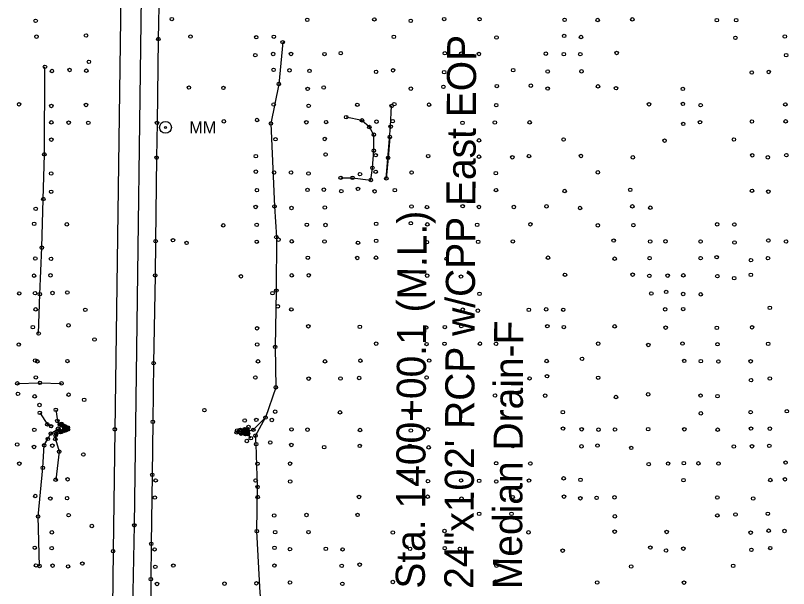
# Model space of a CAD drawing. Extents: x 20503438 to 20508873, y 7964251 to 7984667.
# Drawn here: x 20506686.4 to 20507132.2, y 7972709.2 to 7973039.7 of the extents above; entities that cross this region are included whole.
import ezdxf

# ---------------------------------------------------------------- set-up
doc = ezdxf.new("R2010")
doc.units = 0
for name, color, linetype in [('SurBreakLine', 7, 'Continuous'), ('SurConcreteSlab', 7, 'Continuous'), ('SurDikeDam', 7, 'Continuous'), ('SurDrainageArrowDown', 7, 'Continuous'), ('SurDrainageArrowUp', 7, 'Continuous'), ('SurEdgeRoadPaved', 7, 'Continuous'), ('SurPointsNonDTM', 7, 'Continuous'), ('SurRipRap', 7, 'Continuous'), ('SurRoadPoints', 7, 'Continuous'), ('SurSurveyPoints', 7, 'Continuous'), ('SurTxtDrainage', 7, 'Continuous')]:
    doc.layers.add(name, color=color, linetype=linetype)

msp = doc.modelspace()

# ---------------------------------------------------------------- linework, layer by layer
at = {"layer": 'SurBreakLine'}
for points in [[(20506748.06, 7973121.35), (20506742.68, 7972730.78), (20506738.51, 7972374.69), (20506737.86, 7972337.8), (20506736.71, 7972242.37), (20506735.23, 7972125.23), (20506734.95, 7972091.62), (20506733.69, 7971999.07), (20506733.06, 7971941.23), (20506731.39, 7971811.28), (20506730.1, 7971695.4), (20506729.05, 7971627.9), (20506728.3, 7971561.44), (20506726.5, 7971429.38), (20506726.18, 7971406.05), (20506723.05, 7971149.78), (20506722.41, 7971105.59), (20506719.46, 7970853.94), (20506718.67, 7970817.35), (20506718.46, 7970790.57), (20506717.85, 7970756.37), (20506717.5, 7970726.21), (20506716.72, 7970686.1), (20506716.2, 7970609.97)], [(20506902.29, 7972969.57), (20506901.26, 7972957.53), (20506900.23, 7972945.71), (20506902.74, 7972975.56), (20506903.3, 7972987.46)], [(20506709.69, 7972812.25), (20506710.56, 7972805.83), (20506711.93, 7972803.74), (20506712.96, 7972804.17), (20506716.58, 7972802.08), (20506716.65, 7972800.88), (20506715.37, 7972800.39), (20506713.02, 7972799.51), (20506712.61, 7972799.35), (20506710.67, 7972799.21), (20506709.77, 7972798.39), (20506709.53, 7972797.45), (20506709.4, 7972795.41), (20506711.58, 7972788.13), (20506709.59, 7972771.97)], [(20506822.14, 7972795.93), (20506820.5, 7972798.32), (20506816.48, 7972798.48), (20506813.96, 7972799.22), (20506814.25, 7972800.33), (20506815.9, 7972800.7), (20506818.75, 7972800.97), (20506820.14, 7972800.73), (20506820.73, 7972802.35)], [(20506820.04, 7972800.39), (20506818.39, 7972800.57), (20506816.76, 7972800.22), (20506816.75, 7972799), (20506818.25, 7972798.65), (20506820.05, 7972798.69)]]:
    msp.add_lwpolyline(points, dxfattribs=at)
at = {"layer": 'SurConcreteSlab'}
msp.add_lwpolyline([(20506712.72, 7972803.64), (20506714.66, 7972802.52), (20506715.82, 7972802.12), (20506715.83, 7972800.79), (20506714.63, 7972800.55), (20506712.72, 7972799.78), (20506712.86, 7972799.57), (20506714.62, 7972800.21), (20506716.55, 7972800.87), (20506716.48, 7972801.97), (20506714.59, 7972802.94), (20506713.02, 7972803.84)], close=True, dxfattribs=at)
at = {"layer": 'SurDikeDam'}
msp.add_lwpolyline([(20506687.48, 7972827.52), (20506700.48, 7972827.81), (20506712.95, 7972827.51)], dxfattribs=at)
at = {"layer": 'SurDrainageArrowDown'}
for points in [[(20506699.75, 7972856.23), (20506700.41, 7972878.95), (20506701.62, 7972905.78), (20506702.43, 7972933.79), (20506703.04, 7972959.56), (20506703.41, 7973010.04)], [(20506700.46, 7972810.52), (20506704.78, 7972803.86), (20506706.93, 7972802.78)], [(20506826.98, 7972459.02), (20506824.48, 7972477.91), (20506824.99, 7972502.72), (20506827.82, 7972521.34), (20506830.89, 7972543.69), (20506830.95, 7972545.27), (20506830.12, 7972552.4), (20506832.82, 7972594.42), (20506831.84, 7972643.37), (20506829.67, 7972686.95), (20506827.45, 7972706.67), (20506825.55, 7972742.26), (20506826.01, 7972767.79), (20506825.18, 7972792.47), (20506824.77, 7972797.35), (20506830.56, 7972807.78)], [(20506700.24, 7972722.19), (20506699.43, 7972750.76), (20506702.18, 7972778.8), (20506702.96, 7972791.78), (20506705.03, 7972795.48), (20506706.74, 7972798.56), (20506710.93, 7972801.36), (20506712.61, 7972801.55)]]:
    msp.add_lwpolyline(points, dxfattribs=at)
at = {"layer": 'SurDrainageArrowUp'}
msp.add_lwpolyline([(20506840.5, 7973024.2), (20506838.24, 7973000.1), (20506833.69, 7972977.35), (20506835.79, 7972929.55), (20506836.84, 7972911.84), (20506836.8, 7972881.02), (20506836.12, 7972848.53), (20506836.55, 7972825.2), (20506830.56, 7972807.78), (20506823.52, 7972800.76), (20506820.26, 7972799.73)], dxfattribs=at)
at = {"layer": 'SurEdgeRoadPaved'}
for points in [[(20506751.49, 7972456.42), (20506752.22, 7972492.22), (20506752.7, 7972565.53), (20506753.28, 7972607.69), (20506753.83, 7972675.47), (20506754.2, 7972707.31), (20506754.96, 7972745.65), (20506760.25, 7973137.58)], [(20506769.17, 7973054.72), (20506768.76, 7973026.07), (20506768, 7972977.69), (20506767.76, 7972957.69), (20506767.23, 7972909.5), (20506766.94, 7972889.75), (20506766.06, 7972839.14), (20506765.62, 7972805.36), (20506765.25, 7972774.74), (20506764.67, 7972734.97), (20506764.44, 7972714.59), (20506764.36, 7972675.65), (20506763.96, 7972642.28), (20506764.05, 7972609.2), (20506763.92, 7972562.95), (20506763.79, 7972536.03), (20506764, 7972481.17), (20506764.12, 7972460.5)]]:
    msp.add_lwpolyline(points, dxfattribs=at)
at = {"layer": 'SurPointsNonDTM'}
msp.add_circle((20506743.65, 7972801.01), 1, dxfattribs=at)
at = {"layer": 'SurRipRap'}
msp.add_lwpolyline([(20506873.93, 7972946.06), (20506880.75, 7972946.05), (20506891.29, 7972944.75), (20506892.22, 7972951.81), (20506893.02, 7972961.68), (20506893.05, 7972970.89), (20506890.45, 7972975.31), (20506886.18, 7972979.16), (20506877.07, 7972981)], dxfattribs=at)
at = {"layer": 'SurRoadPoints'}
for radius in [3.43, 0.571]:
    msp.add_circle((20506772.91, 7972975.12), radius, dxfattribs=at)
at = {"layer": 'SurSurveyPoints'}
for centre in [(20506698.02, 7973036.59), (20506776.53, 7973037.57), (20506854.63, 7973037.1), (20506893.33, 7973037.36), (20506914.33, 7973036.54), (20506933.58, 7973037.56), (20506954.02, 7973037.47), (20507003.03, 7973037.14), (20507022.15, 7973037), (20507042.08, 7973037.4), (20507090.86, 7973036.93), (20507101.99, 7973036.94), (20506698.49, 7973027.45), (20506727.06, 7973028.07), (20506787.33, 7973027.47), (20506825.23, 7973027.09), (20506835.36, 7973027.37), (20506904.6, 7973027.36), (20506963.77, 7973026.96), (20507002.77, 7973027.87), (20507012.49, 7973027.21), (20507101.56, 7973026.75), (20507130.05, 7973027.53), (20506768.76, 7973026.07), (20506840.5, 7973024.2), (20506873.96, 7973017.93), (20506933.98, 7973017.87), (20507033.06, 7973018.04), (20506824.7, 7973016.79), (20506834.96, 7973017.44), (20506845.25, 7973017.44), (20506864.58, 7973017.37), (20506943.45, 7973017.65), (20506953.64, 7973017.44), (20506992.22, 7973017.6), (20507002.63, 7973017.33), (20507012.09, 7973017.35), (20507130.8, 7973016.78), (20506703.41, 7973010.04), (20506728.73, 7973012.91), (20506707.41, 7973007.59), (20506717.59, 7973008.22), (20506727.27, 7973007.81), (20506835.22, 7973008.28), (20506844.38, 7973008.05), (20506855.93, 7973007.69), (20506894.34, 7973007.18), (20506904.15, 7973008.02), (20506933.6, 7973006.99), (20506973.38, 7973008.11), (20506993.3, 7973007.35), (20507012.82, 7973007.4), (20507110.97, 7973006.79), (20507120.78, 7973007.08), (20506838.24, 7973000.1), (20506786.41, 7972998.06), (20506806.29, 7972997.88), (20506854.86, 7972997.3), (20506864.12, 7972998.09), (20506914.38, 7972997.46), (20506933.17, 7972998.51), (20506963.98, 7972998.92), (20506983.59, 7972999.14), (20506993.31, 7972997.5), (20507022.31, 7972998.78), (20507032.72, 7972997.69), (20507071.19, 7972997.3), (20506688.47, 7972988.44), (20506707.09, 7972987.46), (20506727.03, 7972988.04), (20506835.31, 7972988.33), (20506855.42, 7972987.55), (20506883.52, 7972988.17), (20506903.3, 7972987.46), (20506904.84, 7972988.5), (20506924.89, 7972988.19), (20506963.62, 7972987.91), (20507051.69, 7972988.42), (20507071.27, 7972988.66), (20507081.47, 7972987.93), (20507130.37, 7972988.35), (20506707.06, 7972977.99), (20506717.05, 7972977.87), (20506728.38, 7972977.71), (20506768, 7972977.69), (20506806.57, 7972978.58), (20506825.72, 7972979.36), (20506854.11, 7972978.03), (20506865.5, 7972978.16), (20506877.07, 7972981), (20506886.18, 7972979.16), (20506894.56, 7972978.38), (20506903.9, 7972978.69), (20506944.2, 7972977.75), (20506962.83, 7972977.94), (20506982.92, 7972978.02), (20507081.09, 7972978.08), (20507111.06, 7972978.5), (20507130.5, 7972978.6), (20506833.69, 7972977.35), (20506890.45, 7972975.31), (20506902.74, 7972975.56), (20507071.46, 7972977.11), (20506893.05, 7972970.89), (20506902.29, 7972969.57), (20506707.08, 7972968.06), (20506836.3, 7972968.28), (20506864.74, 7972968.44), (20506953.67, 7972967.64), (20507002.46, 7972968.16), (20507060.69, 7972967.47), (20507100.69, 7972968.11), (20506893.02, 7972961.68), (20506703.04, 7972959.56), (20506767.76, 7972957.69), (20506824.96, 7972958.49), (20506865.22, 7972959.51), (20506894.13, 7972959.06), (20506901.26, 7972957.53), (20506924.37, 7972958.57), (20506953.69, 7972958.22), (20506972.88, 7972957.87), (20506982.51, 7972958.56), (20507012.44, 7972958.64), (20507042.41, 7972957.84), (20507111.24, 7972959.01), (20507120.27, 7972957.88), (20507130.94, 7972959.12), (20506892.22, 7972951.81), (20506706.97, 7972948.51), (20506825.01, 7972949.59), (20506835.52, 7972949.1), (20506845.3, 7972949.09), (20506855.35, 7972948.54), (20506885.03, 7972948.11), (20506894.1, 7972949.52), (20506914.81, 7972949.07), (20506963.38, 7972948.74), (20507022.18, 7972949.17), (20506873.93, 7972946.06), (20506880.75, 7972946.05), (20506891.29, 7972944.75), (20506900.23, 7972945.71), (20506707, 7972938), (20506825.62, 7972938.91), (20506854.82, 7972939.05), (20506864.2, 7972939.21), (20506874.28, 7972938.34), (20506883.89, 7972939.63), (20506893.47, 7972938.26), (20506905.14, 7972938.93), (20506963.5, 7972938.96), (20507003.11, 7972938.4), (20507040.9, 7972939.09), (20507111.11, 7972938.57), (20507120.52, 7972938.05), (20506702.43, 7972933.79), (20506824.91, 7972929.21), (20506835.79, 7972929.55), (20506845.55, 7972928.65), (20506864.78, 7972928.93), (20506914.73, 7972929.48), (20506923.69, 7972929.16), (20506944.3, 7972929.64), (20506953.64, 7972929.23), (20506973.77, 7972929.22), (20506992.62, 7972929.59), (20507011.98, 7972928.63), (20507042.11, 7972929.56), (20507052.47, 7972928.8), (20506698.07, 7972928.18), (20506914.38, 7972919.85), (20506697.19, 7972919.48), (20506716, 7972919.21), (20506806.21, 7972918.6), (20506825.48, 7972918.89), (20506854.41, 7972918.96), (20506865.17, 7972918.84), (20506894.35, 7972919.48), (20506923.85, 7972919.18), (20506952.61, 7972918.93), (20506983.33, 7972919.24), (20507022.22, 7972918.67), (20507042.72, 7972918.76), (20507090.99, 7972919.25), (20507100.93, 7972919.1), (20506836.84, 7972911.84), (20506767.23, 7972909.5), (20506777.19, 7972910.04), (20506785.06, 7972908.49), (20506825.53, 7972909.17), (20506838.03, 7972910.38), (20506845.7, 7972909.39), (20506864.61, 7972909.32), (20506883.9, 7972908.6), (20506894.4, 7972909.67), (20506923.65, 7972908.96), (20506953.23, 7972909.13), (20506973.16, 7972909.36), (20507031.37, 7972909.84), (20507052.4, 7972909.34), (20507061.25, 7972909.43), (20507081.46, 7972909.29), (20507101.01, 7972908.72), (20507120.54, 7972909.86), (20507130.75, 7972909.29), (20506701.62, 7972905.78), (20506697.81, 7972899.53), (20506706.89, 7972899.3), (20506855.01, 7972899.94), (20506883.47, 7972899.82), (20506894.27, 7972899.99), (20506934.98, 7972899.36), (20506993.45, 7972899.97), (20507031.89, 7972899.38), (20507052.05, 7972899.72), (20507081.5, 7972899.67), (20507090.77, 7972900.23), (20507110.53, 7972898.55), (20507120.3, 7972899.73), (20506697.13, 7972889.58), (20506706.6, 7972889.82), (20506766.94, 7972889.75), (20506816.39, 7972889.24), (20506845.71, 7972889.77), (20506855.5, 7972889.82), (20506923.8, 7972889.62), (20506943.3, 7972889.08), (20507003.25, 7972890.13), (20507042.29, 7972890.19), (20507051.92, 7972889.53), (20507062.48, 7972889.63), (20507071.52, 7972889.77), (20507091.15, 7972889.29), (20507110.44, 7972890.06), (20507100.86, 7972888.15), (20506707.76, 7972879.63), (20506716.27, 7972879.88), (20506834.62, 7972879.54), (20506836.8, 7972881.02), (20507061.64, 7972880.25), (20506688.57, 7972879.38), (20506697.65, 7972879.49), (20506700.41, 7972878.95), (20506953.97, 7972879.17), (20507053.04, 7972879.3), (20507071.4, 7972879.05), (20507081.55, 7972878.81), (20506837.67, 7972871.96), (20507121.39, 7972871.07), (20506698.04, 7972870.19), (20506726.65, 7972869.94), (20506845.44, 7972870.15), (20506944.31, 7972870.05), (20506953, 7972869.46), (20506982.45, 7972869.88), (20506992.44, 7972870.19), (20507002.27, 7972869.95), (20507061.06, 7972870.23), (20507071.4, 7972870.34), (20506696.43, 7972859.89), (20506716.97, 7972860.94), (20506825.71, 7972859.25), (20506855.29, 7972860.4), (20506884.96, 7972860.13), (20506923.27, 7972859.68), (20506933.99, 7972859.96), (20506943.48, 7972860.5), (20506993.06, 7972860.45), (20507002.62, 7972859.96), (20507031.94, 7972860.38), (20507061.3, 7972859.63), (20507090.82, 7972859.56), (20507111.17, 7972859.83), (20506699.75, 7972856.23), (20506731.93, 7972852.79), (20506688.27, 7972849.88), (20506825.78, 7972849.94), (20506836.12, 7972848.53), (20506894.39, 7972850.44), (20506923.45, 7972850.16), (20506933.81, 7972850.35), (20506954.21, 7972850.39), (20506963.52, 7972850.29), (20507022.41, 7972850.44), (20507051.3, 7972849.65), (20507071.04, 7972850.45), (20507091.22, 7972850.07), (20507120.43, 7972850.28), (20506697.76, 7972840.7), (20506699.02, 7972840.2), (20506716.35, 7972840.36), (20506826.21, 7972840.2), (20506864.88, 7972840.2), (20506885.31, 7972840.56), (20506924.92, 7972840.64), (20506992.72, 7972840.38), (20507013.11, 7972841.69), (20507072.03, 7972840.45), (20507081.63, 7972840.32), (20507091.75, 7972840.15), (20507110.33, 7972840.24), (20506766.06, 7972839.14), (20506698.1, 7972830.94), (20506824.71, 7972830.86), (20506884.59, 7972830.59), (20506923.46, 7972830.92), (20506992.91, 7972831.62), (20507022.4, 7972830.75), (20506687.48, 7972827.52), (20506700.48, 7972827.81), (20506712.95, 7972827.51), (20506855.46, 7972830.24), (20506873.85, 7972830.31), (20506982.86, 7972830.37), (20507110.56, 7972829.34), (20507121.39, 7972830.32), (20506836.55, 7972825.2), (20506687.83, 7972821.45), (20506697.47, 7972820.03), (20506717.02, 7972820.98), (20506726.02, 7972818.04), (20506962.93, 7972820.49), (20506991.84, 7972820.45), (20507032.72, 7972819.64), (20507051.2, 7972821.18), (20507081.46, 7972820.46), (20507091.2, 7972820.14), (20506700.24, 7972815.06), (20506700.46, 7972810.52), (20506709.69, 7972812.25), (20506795.34, 7972812.08), (20506836.13, 7972811.18), (20506873.54, 7972810.79), (20506914.42, 7972810.82), (20507002.05, 7972810.87), (20507081.59, 7972810.22), (20507110.32, 7972810.93), (20507131.18, 7972811.43), (20506704.78, 7972803.86), (20506710.56, 7972805.83), (20506711.93, 7972803.74), (20506712.96, 7972804.17), (20506713.02, 7972803.84), (20506765.62, 7972805.36), (20506818.57, 7972806.1), (20506825.27, 7972806.43), (20506830.56, 7972807.78), (20506834.23, 7972806.42), (20506697.25, 7972800.71), (20506706.93, 7972802.78), (20506710.93, 7972801.36), (20506712.61, 7972801.55), (20506712.61, 7972799.35), (20506712.72, 7972803.64), (20506712.72, 7972799.78), (20506712.86, 7972799.57), (20506713.02, 7972799.51), (20506714.59, 7972802.94), (20506714.62, 7972800.21), (20506714.63, 7972800.55), (20506714.66, 7972802.52), (20506715.37, 7972800.39), (20506715.82, 7972802.12), (20506715.83, 7972800.79), (20506716.48, 7972801.97), (20506716.55, 7972800.87), (20506716.58, 7972802.08), (20506716.65, 7972800.88), (20506814.25, 7972800.33), (20506815.9, 7972800.7), (20506816.76, 7972800.22), (20506818.39, 7972800.57), (20506818.4, 7972801), (20506818.75, 7972800.97), (20506820.04, 7972800.39), (20506820.14, 7972800.73), (20506820.26, 7972799.73), (20506820.73, 7972802.35), (20506823.52, 7972800.76), (20506845.56, 7972800.96), (20506854.77, 7972800.84), (20506885.05, 7972800.61), (20506914.39, 7972800.3), (20506924.29, 7972801.02), (20507002.14, 7972801.44), (20507012.91, 7972801.02), (20507022.58, 7972800.78), (20507032.1, 7972800.89), (20507051.26, 7972801.13), (20507072.08, 7972801.04), (20507091.29, 7972800.8), (20507110.52, 7972801.44), (20507121.41, 7972801.41), (20506705.03, 7972795.48), (20506706.74, 7972798.56), (20506709.4, 7972795.41), (20506709.53, 7972797.45), (20506709.77, 7972798.39), (20506710.67, 7972799.21), (20506813.96, 7972799.22), (20506816.48, 7972798.48), (20506816.75, 7972799), (20506818.25, 7972798.65), (20506818.98, 7972798.2), (20506820.05, 7972798.69), (20506820.5, 7972798.32), (20506822.14, 7972795.93), (20506824.77, 7972797.35), (20506687.38, 7972792.28), (20506697.04, 7972790.82), (20506702.96, 7972791.78), (20506707.65, 7972791.6), (20506819.79, 7972794.26), (20506825.18, 7972792.47), (20506833.3, 7972793.4), (20506845.45, 7972792), (20506864.37, 7972790.71), (20506884.93, 7972791.45), (20506913.81, 7972791.48), (20506924.69, 7972790.59), (20506973.19, 7972791.43), (20507012.82, 7972791.19), (20507022, 7972791.63), (20507100.6, 7972791.11), (20507111.13, 7972791.23), (20507121.1, 7972791.51), (20506711.58, 7972788.13), (20506725.55, 7972786.47), (20507041.48, 7972790.28), (20506963.59, 7972781.44), (20507071.79, 7972781.51), (20507130.48, 7972781.83), (20506688.63, 7972781.21), (20506702.18, 7972778.8), (20506825.96, 7972781.16), (20506844.74, 7972781.24), (20506983.3, 7972781.28), (20507051.56, 7972780.93), (20507062.72, 7972781.25), (20507080.22, 7972781.38), (20507091.79, 7972781.26), (20506765.25, 7972774.74), (20507002.48, 7972772.74), (20506709.59, 7972771.97), (20506716.44, 7972772.2), (20506767.23, 7972771.55), (20506824.86, 7972771.49), (20506844.82, 7972770.9), (20506914.62, 7972771.66), (20506924.26, 7972771.11), (20506943.35, 7972771.55), (20506953.78, 7972771.31), (20506963.62, 7972770.89), (20506982.48, 7972771.45), (20507012.19, 7972771.91), (20507071.64, 7972771.7), (20507121.7, 7972771.78), (20507130.08, 7972772.18), (20506826.01, 7972767.79), (20506697.8, 7972762.56), (20506706.49, 7972761.07), (20506716.16, 7972761.32), (20506766.73, 7972761.65), (20506826.03, 7972761.96), (20506884.48, 7972762.02), (20506924.06, 7972762.16), (20506943.61, 7972761.06), (20506973.11, 7972761.93), (20507002.7, 7972762.21), (20507012.14, 7972761.25), (20507021.49, 7972761.51), (20507031.85, 7972761.82), (20507091.11, 7972761.72), (20507111.76, 7972761.12), (20506699.43, 7972750.76), (20506717.03, 7972751.54), (20506835.57, 7972751.35), (20506854.18, 7972751.62), (20506883.67, 7972751.65), (20506953.75, 7972752.31), (20506972.44, 7972752.31), (20507032.04, 7972750.81), (20507091.14, 7972751.36), (20507101.6, 7972751.91), (20507120.21, 7972752.32), (20506707.33, 7972741.58), (20506730.42, 7972745.25), (20506754.96, 7972745.65), (20506825.55, 7972742.26), (20506836.13, 7972741.73), (20506855.37, 7972741.76), (20506904.02, 7972741.51), (20506933.8, 7972742.37), (20506982.2, 7972741.6), (20507031.9, 7972742), (20507061.88, 7972741.81), (20507110.32, 7972741.42), (20507120.72, 7972742.56), (20507129.88, 7972742.41), (20506697.51, 7972732.71), (20506707.29, 7972732.47), (20506764.67, 7972734.97), (20506835.76, 7972732.67), (20506933.94, 7972732.51), (20507052.51, 7972732.82), (20507121.62, 7972732.53), (20506742.68, 7972730.78), (20506766.61, 7972731.75), (20506844.69, 7972731.93), (20506865.35, 7972732.11), (20506875.02, 7972731.75), (20506913.95, 7972732.07), (20506942.67, 7972732.12), (20507001.9, 7972731.07), (20507061.54, 7972731.14), (20507071.53, 7972732.21), (20507110.78, 7972731.49), (20506724.96, 7972723.59), (20506698.22, 7972722.54), (20506700.24, 7972722.19), (20506707.78, 7972722.4), (20506716.72, 7972721.96), (20506767.02, 7972721.73), (20506777.39, 7972722.43), (20506835.7, 7972722.44), (20506874.52, 7972722.28), (20506884.85, 7972722.97), (20506963.75, 7972722.4), (20507041.46, 7972721.94), (20507100.26, 7972722.32), (20506764.44, 7972714.59), (20506767.97, 7972711.84), (20506806.91, 7972712.04), (20506825.34, 7972712.22), (20506844.67, 7972712.69), (20506874.89, 7972711.9), (20506904.01, 7972713.01), (20506963.27, 7972713.17), (20507021.8, 7972712.65), (20507071.86, 7972712.6)]:
    msp.add_circle(centre, 1, dxfattribs=at)

# ---------------------------------------------------------------- texts
at = {"layer": 'SurRoadPoints'}
msp.add_text('MM', height=6.995, rotation=360, dxfattribs=at).set_placement((20506786.62, 7972971.62))
at = {"layer": 'SurTxtDrainage'}
for s, p in [('24"x102\' RCP w/CPP East EOP', (20506950.42, 7972708.96)), ('Sta. 1400+00.1 (M.L.)', (20506922.42, 7972709.11)), ('Median Drain-F', (20506978.42, 7972708.81))]:
    msp.add_text(s, height=16.8, rotation=89.6917, dxfattribs=at).set_placement(p)

doc.saveas('drawing.dxf')
